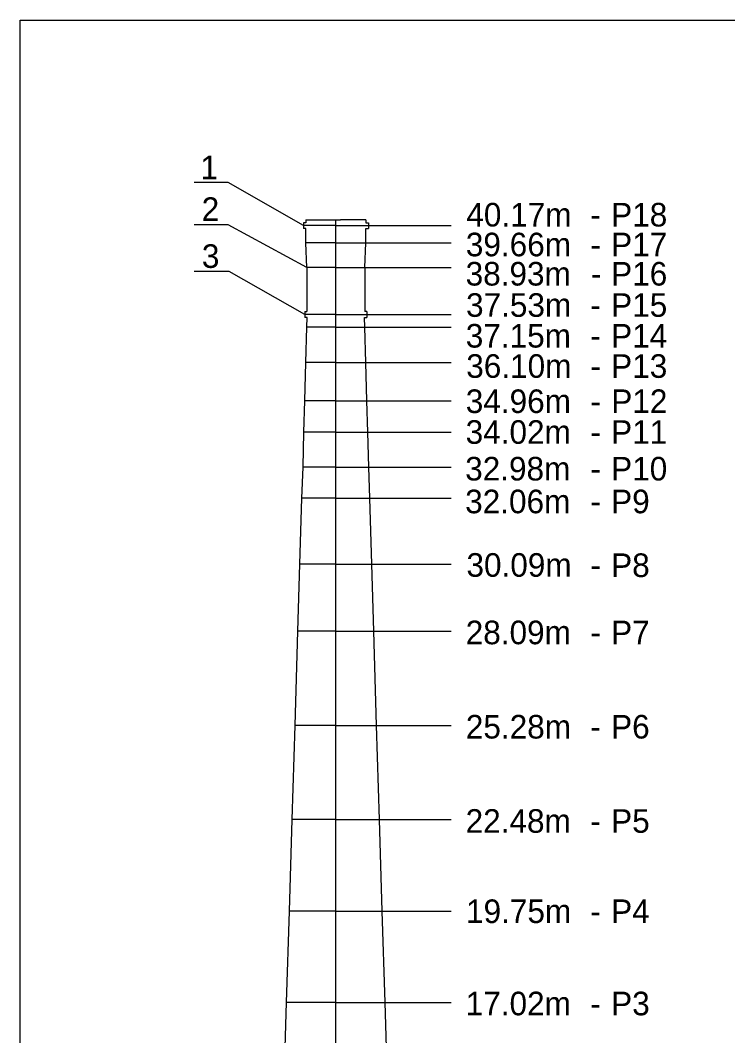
# Model space of a CAD drawing. Extents: x 138 to 264, y -75 to 121.
# Drawn here: x 167.3 to 177.8, y -15.91 to -0.84 of the extents above; entities that cross this region are included whole.
import ezdxf

# ---------------------------------------------------------------- set-up
doc = ezdxf.new("R2010")
doc.units = 0
doc.layers.add('Ramka do drukowania', color=7, linetype='Continuous')
doc.layers.add('Standard', color=7, linetype='Continuous')

msp = doc.modelspace()

# ---------------------------------------------------------------- linework, layer by layer
at = {"layer": 'Ramka do drukowania'}
for p, q in [((167.297, -30.544), (167.297, -0.844)), ((167.297, -0.844), (188.297, -0.844))]:
    msp.add_line(p, q, dxfattribs=at)
at = {"layer": 'Standard'}
for p, q in [((171.498, -3.848), (171.498, -3.89)), ((171.535, -3.848), (171.498, -3.848)), ((171.981, -3.89), (171.498, -3.89)), ((171.498, -3.89), (171.498, -3.933)), ((171.535, -3.806), (171.535, -3.848)), ((171.535, -3.806), (172.05, -3.806)), ((171.981, -23.89), (171.981, -3.806)), ((171.981, -3.89), (173.691, -3.89)), ((172.426, -3.806), (172.05, -3.806)), ((172.426, -3.806), (172.426, -3.848)), ((172.426, -3.848), (172.463, -3.848)), ((172.463, -3.848), (172.463, -3.89)), ((172.463, -3.89), (172.463, -3.933)), ((171.535, -3.933), (171.498, -3.933)), ((171.535, -4.146), (171.535, -3.933)), ((172.426, -3.933), (172.463, -3.933)), ((172.426, -4.146), (172.426, -3.933)), ((171.981, -4.146), (171.535, -4.146)), ((171.55, -4.509), (171.535, -4.146)), ((171.981, -4.146), (173.691, -4.146)), ((172.411, -4.509), (172.426, -4.146)), ((171.981, -4.509), (171.55, -4.509)), ((171.55, -4.509), (171.55, -5.163)), ((171.981, -4.509), (173.691, -4.509)), ((172.411, -4.509), (172.411, -5.163)), ((171.52, -5.163), (171.52, -5.207)), ((171.52, -5.163), (171.55, -5.163)), ((171.981, -5.207), (171.52, -5.207)), ((171.52, -5.207), (171.52, -5.251)), ((171.554, -5.251), (171.52, -5.251)), ((171.55, -5.395), (171.554, -5.251)), ((171.981, -5.207), (173.691, -5.207)), ((172.411, -5.395), (172.407, -5.251)), ((172.407, -5.251), (172.441, -5.251)), ((172.441, -5.163), (172.411, -5.163)), ((172.441, -5.163), (172.441, -5.207)), ((172.441, -5.207), (172.441, -5.251)), ((171.535, -5.92), (171.55, -5.395)), ((171.981, -5.395), (171.55, -5.395)), ((171.981, -5.395), (173.691, -5.395)), ((172.426, -5.92), (172.411, -5.395)), ((171.52, -6.488), (171.535, -5.92)), ((171.981, -5.92), (171.535, -5.92)), ((171.981, -5.92), (173.691, -5.92)), ((172.441, -6.488), (172.426, -5.92)), ((171.505, -6.956), (171.52, -6.488)), ((171.981, -6.488), (171.52, -6.488)), ((171.981, -6.488), (173.691, -6.488)), ((172.456, -6.956), (172.441, -6.488)), ((171.493, -7.473), (171.505, -6.956)), ((171.981, -6.956), (171.505, -6.956)), ((171.981, -6.956), (173.691, -6.956)), ((172.468, -7.473), (172.456, -6.956)), ((171.475, -7.932), (171.493, -7.473)), ((171.981, -7.473), (171.493, -7.473)), ((171.981, -7.473), (173.691, -7.473)), ((172.486, -7.932), (172.468, -7.473)), ((171.448, -8.913), (171.475, -7.932)), ((171.981, -7.932), (171.475, -7.932)), ((171.981, -7.932), (173.691, -7.932)), ((172.513, -8.913), (172.486, -7.932)), ((171.418, -9.906), (171.448, -8.913)), ((171.981, -8.913), (171.448, -8.913)), ((171.981, -8.913), (173.691, -8.913)), ((172.543, -9.906), (172.513, -8.913)), ((171.378, -11.308), (171.418, -9.906)), ((171.981, -9.906), (171.418, -9.906)), ((171.981, -9.906), (173.691, -9.906)), ((172.583, -11.308), (172.543, -9.906)), ((171.333, -12.699), (171.378, -11.308)), ((171.981, -11.308), (171.378, -11.308)), ((171.981, -11.308), (173.691, -11.308)), ((172.628, -12.699), (172.583, -11.308)), ((171.291, -14.058), (171.333, -12.699)), ((171.981, -12.699), (171.333, -12.699)), ((171.981, -12.699), (173.691, -12.699)), ((172.67, -14.058), (172.628, -12.699)), ((171.249, -15.416), (171.291, -14.058)), ((171.981, -14.058), (171.291, -14.058)), ((171.981, -14.058), (173.691, -14.058)), ((172.712, -15.416), (172.67, -14.058)), ((171.206, -16.784), (171.249, -15.416)), ((171.981, -15.416), (171.249, -15.416)), ((171.981, -15.416), (173.691, -15.416)), ((172.755, -16.784), (172.712, -15.416))]:
    msp.add_line(p, q, dxfattribs=at)
for points in [[(171.498, -3.89), (170.384, -3.251), (169.879, -3.251)], [(171.55, -4.509), (170.384, -3.878), (169.879, -3.878)], [(171.52, -5.207), (170.396, -4.571), (169.879, -4.571)]]:
    msp.add_lwpolyline(points, dxfattribs=at)

# ---------------------------------------------------------------- texts
for s, p in [('1', (169.971, -3.202)), ('2', (169.989, -3.82)), ('40.17m', (173.917, -3.903)), ('P18', (176.067, -3.903)), ('-', (175.756, -3.903)), ('39.66m', (173.91, -4.345)), ('P17', (176.067, -4.345)), ('3', (169.992, -4.517)), ('-', (175.759, -4.345)), ('38.93m', (173.907, -4.779)), ('P16', (176.067, -4.779)), ('-', (175.766, -4.779)), ('37.53m', (173.913, -5.243)), ('P15', (176.067, -5.243)), ('-', (175.756, -5.243)), ('37.15m', (173.909, -5.699)), ('P14', (176.067, -5.699)), ('-', (175.756, -5.699)), ('36.10m', (173.916, -6.148)), ('P13', (176.067, -6.148)), ('-', (175.759, -6.148)), ('34.96m', (173.909, -6.67)), ('P12', (176.069, -6.67)), ('-', (175.759, -6.67)), ('34.02m', (173.907, -7.127)), ('P11', (176.067, -7.127)), ('-', (175.759, -7.127)), ('32.98m', (173.9, -7.671)), ('P10', (176.067, -7.671)), ('-', (175.759, -7.671)), ('32.06m', (173.9, -8.157)), ('P9', (176.067, -8.157)), ('-', (175.759, -8.157)), ('30.09m', (173.919, -9.099)), ('P8', (176.067, -9.103)), ('-', (175.759, -9.099)), ('28.09m', (173.908, -10.1)), ('P7', (176.067, -10.1)), ('-', (175.759, -10.1)), ('25.28m', (173.91, -11.499)), ('P6', (176.066, -11.499)), ('-', (175.756, -11.499)), ('22.48m', (173.907, -12.897)), ('P5', (176.067, -12.897)), ('-', (175.756, -12.897)), ('19.75m', (173.913, -14.236)), ('P4', (176.067, -14.236)), ('-', (175.756, -14.236)), ('17.02m', (173.908, -15.605)), ('P3', (176.067, -15.605)), ('-', (175.756, -15.605))]:
    msp.add_text(s, height=0.35, dxfattribs=at).set_placement(p)

doc.saveas('drawing.dxf')
